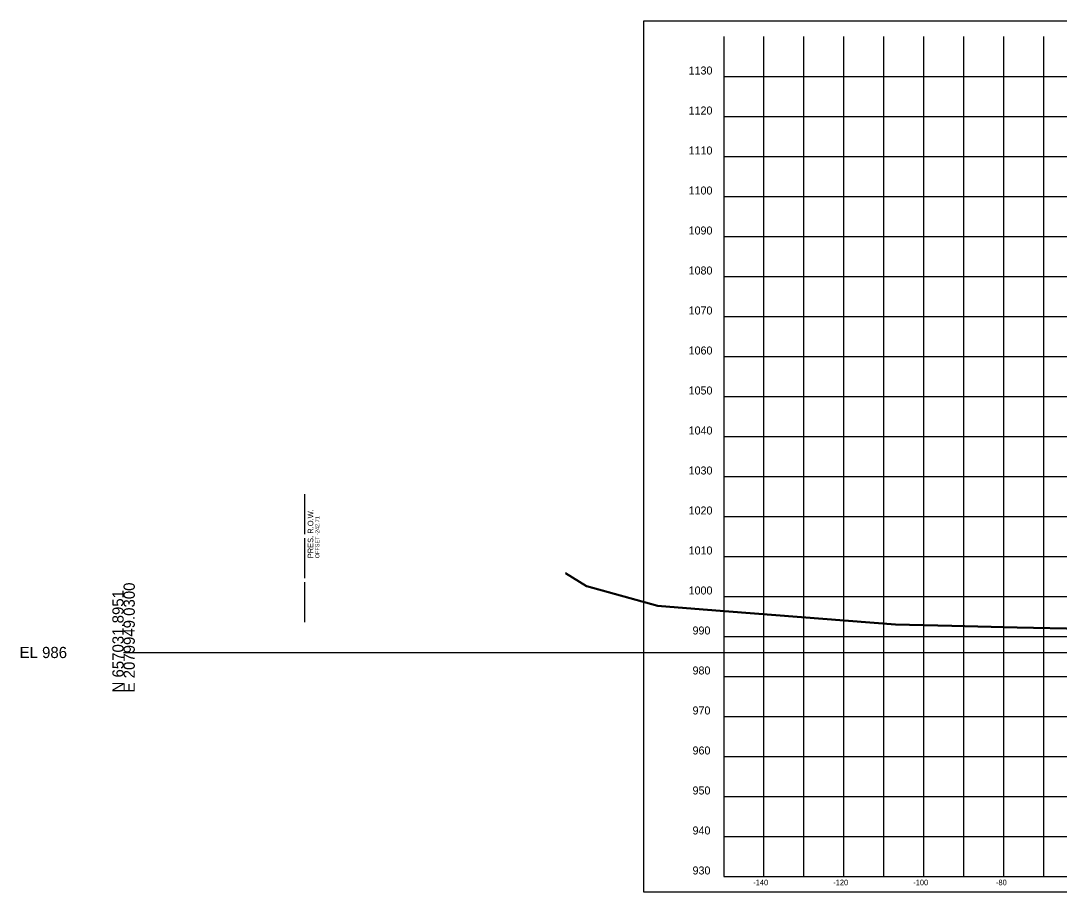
# Model space of a CAD drawing. Extents: x 1131015 to 1136271, y 133453 to 174329.
# Drawn here: x 1132014.8 to 1132274.3, y 156107.7 to 156325.6 of the extents above; entities that cross this region are included whole.
import ezdxf

# ---------------------------------------------------------------- set-up
doc = ezdxf.new("R2010")
doc.units = 0
for name, color, linetype in [('DESIGN - SHEET - Corner Text', 7, 'Continuous'), ('DESIGN - SHEET - Light Grid', 7, 'Continuous'), ('DESIGN - SHEET - Linework', 7, 'Continuous'), ('DESIGN - SHEET - Plot Shape', 7, 'Continuous'), ('SURVEY - GROUND - Bottom of Topsoil Layer', 7, 'Continuous'), ('SURVEY - GROUND - Top of Ground', 7, 'Continuous'), ('SURVEY - PROPERTY - ROW Lines', 7, 'Continuous'), ('SURVEY - PROPERTY - ROW Lines Text', 7, 'Continuous')]:
    doc.layers.add(name, color=color, linetype=linetype)

msp = doc.modelspace()

# ---------------------------------------------------------------- linework, layer by layer
at = {"layer": 'DESIGN - SHEET - Light Grid'}
msp.add_line((1132040.46, 156167.66), (1132340.46, 156167.66), dxfattribs=at)
at = {"layer": 'DESIGN - SHEET - Linework'}
for p, q in [((1132200.46, 156111.66), (1132200.46, 156321.66)), ((1132210.46, 156111.66), (1132210.46, 156321.66)), ((1132220.46, 156111.66), (1132220.46, 156321.66)), ((1132230.46, 156111.66), (1132230.46, 156321.66)), ((1132240.46, 156111.66), (1132240.46, 156321.66)), ((1132250.46, 156111.66), (1132250.46, 156321.66)), ((1132260.46, 156111.66), (1132260.46, 156321.66)), ((1132270.46, 156111.66), (1132270.46, 156321.66)), ((1132190.46, 156311.66), (1132490.46, 156311.66)), ((1132190.46, 156301.66), (1132490.46, 156301.66)), ((1132190.46, 156291.66), (1132490.46, 156291.66)), ((1132190.46, 156281.66), (1132490.46, 156281.66)), ((1132190.46, 156271.66), (1132490.46, 156271.66)), ((1132190.46, 156261.66), (1132490.46, 156261.66)), ((1132190.46, 156251.66), (1132490.46, 156251.66)), ((1132190.46, 156241.66), (1132490.46, 156241.66)), ((1132190.46, 156231.66), (1132490.46, 156231.66)), ((1132190.46, 156221.66), (1132490.46, 156221.66)), ((1132190.46, 156211.66), (1132490.46, 156211.66)), ((1132190.46, 156201.66), (1132490.46, 156201.66)), ((1132190.46, 156191.66), (1132490.46, 156191.66)), ((1132190.46, 156181.66), (1132490.46, 156181.66)), ((1132190.46, 156171.66), (1132490.46, 156171.66)), ((1132190.46, 156161.66), (1132490.46, 156161.66)), ((1132190.46, 156151.66), (1132490.46, 156151.66)), ((1132190.46, 156141.66), (1132490.46, 156141.66)), ((1132190.46, 156131.66), (1132490.46, 156131.66)), ((1132190.46, 156121.66), (1132490.46, 156121.66))]:
    msp.add_line(p, q, dxfattribs=at)
msp.add_lwpolyline([(1132190.46, 156321.66), (1132190.46, 156111.66), (1132490.46, 156111.66), (1132490.46, 156321.66)], dxfattribs=at)
at = {"layer": 'DESIGN - SHEET - Plot Shape'}
msp.add_lwpolyline([(1132170.46, 156325.6), (1132510.46, 156325.6), (1132510.46, 156107.72), (1132170.46, 156107.72)], close=True, dxfattribs=at)
at = {"layer": 'SURVEY - GROUND - Bottom of Topsoil Layer'}
for p, q in [((1132150.92, 156187.37), (1132156.16, 156184.14)), ((1132156.16, 156184.14), (1132173.91, 156179.2)), ((1132173.91, 156179.2), (1132185.32, 156178.32)), ((1132185.32, 156178.32), (1132233.4, 156174.58)), ((1132233.4, 156174.58), (1132247.52, 156174.25)), ((1132247.52, 156174.25), (1132263.79, 156173.84)), ((1132263.79, 156173.84), (1132292.68, 156173.18))]:
    msp.add_line(p, q, dxfattribs=at)
at = {"layer": 'SURVEY - GROUND - Top of Ground'}
for p, q in [((1132150.92, 156187.62), (1132156.16, 156184.39)), ((1132156.16, 156184.39), (1132173.91, 156179.45)), ((1132173.91, 156179.45), (1132185.32, 156178.57)), ((1132185.32, 156178.57), (1132233.4, 156174.83)), ((1132233.4, 156174.83), (1132247.52, 156174.5)), ((1132247.52, 156174.5), (1132263.79, 156174.09)), ((1132263.79, 156174.09), (1132292.68, 156173.43))]:
    msp.add_line(p, q, dxfattribs=at)
at = {"layer": 'SURVEY - PROPERTY - ROW Lines'}
for p, q in [((1132085.74, 156197.21), (1132085.74, 156207.21)), ((1132085.74, 156186.21), (1132085.74, 156196.21)), ((1132085.74, 156175.21), (1132085.74, 156185.21))]:
    msp.add_line(p, q, dxfattribs=at)

# ---------------------------------------------------------------- texts
at = {"layer": 'DESIGN - SHEET - Corner Text'}
for s, height, p in [('1130', 2, (1132181.7, 156312.16)), ('1120', 2, (1132181.7, 156302.16)), ('1110', 2, (1132181.7, 156292.16)), ('1100', 2, (1132181.7, 156282.16)), ('1090', 2, (1132181.7, 156272.16)), ('1080', 2, (1132181.7, 156262.16)), ('1070', 2, (1132181.7, 156252.16)), ('1060', 2, (1132181.7, 156242.16)), ('1050', 2, (1132181.7, 156232.16)), ('1040', 2, (1132181.7, 156222.16)), ('1030', 2, (1132181.7, 156212.16)), ('1020', 2, (1132181.7, 156202.16)), ('1010', 2, (1132181.7, 156192.16)), ('1000', 2, (1132181.7, 156182.16)), ('990', 2, (1132182.68, 156172.16)), ('980', 2, (1132182.68, 156162.16)), ('970', 2, (1132182.68, 156152.16)), ('960', 2, (1132182.68, 156142.16)), ('950', 2, (1132182.68, 156132.16)), ('940', 2, (1132182.68, 156122.16)), ('930', 2, (1132182.68, 156112.16)), ('-140', 1.4, (1132197.83, 156109.46)), ('-120', 1.4, (1132217.83, 156109.46)), ('-100', 1.4, (1132237.83, 156109.46)), ('-80', 1.4, (1132258.51, 156109.46))]:
    msp.add_text(s, height=height, dxfattribs=at).set_placement(p)
at = {"layer": 'DESIGN - SHEET - Light Grid'}
for s, p in [('E 2079949.0300', (1132043.26, 156157.66)), ('N 657031.8951', (1132040.46, 156157.66))]:
    msp.add_text(s, height=2.8, rotation=90, dxfattribs=at).set_placement(p)
msp.add_text('EL 986', height=2.8, dxfattribs=at).set_placement((1132014.46, 156166.26))
at = {"layer": 'SURVEY - PROPERTY - ROW Lines Text'}
for s, height, p in [('PRES. R.O.W.', 1.4, (1132087.89, 156191.21)), ('OFFSET -242.71', 1, (1132089.39, 156191.21))]:
    msp.add_text(s, height=height, rotation=90, dxfattribs=at).set_placement(p)

doc.saveas('drawing.dxf')
